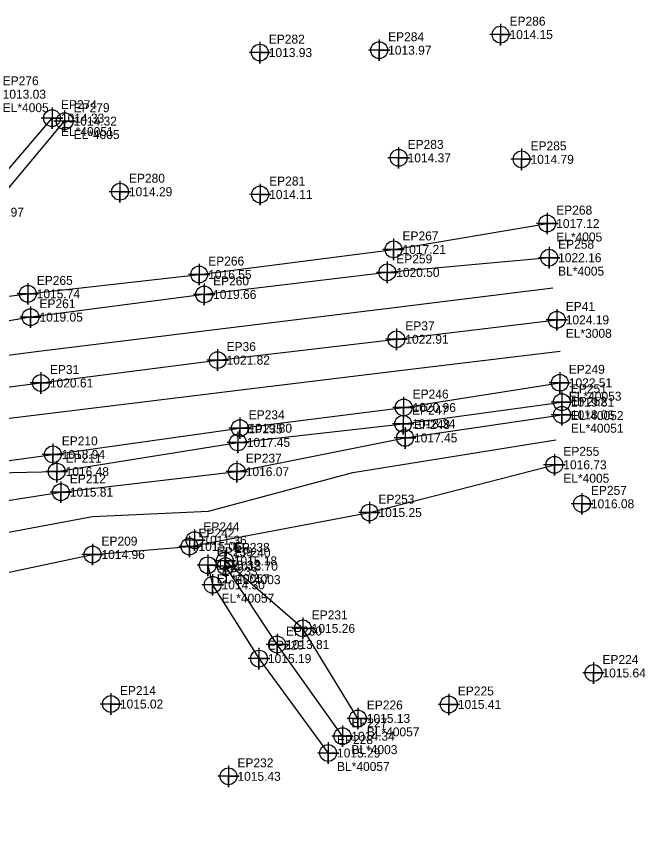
# Model space of a CAD drawing. Extents: x 1382561 to 1383039, y 884068 to 884307.
# Drawn here: x 1382864 to 1383039.5, y 884076 to 884306.8 of the extents above; entities that cross this region are included whole.
import ezdxf

# ---------------------------------------------------------------- set-up
doc = ezdxf.new("R2010")
doc.units = 0
for name, color, linetype in [('Exist DTM Breakline', 7, 'Continuous'), ('Exist DTM Breakline Cogo Comment', 7, 'Continuous'), ('Exist DTM Breakline Cogo Elevation', 7, 'Continuous'), ('Exist DTM Breakline Cogo Number', 7, 'Continuous'), ('Exist DTM Breakline Cogo Point CELL', 7, 'Continuous'), ('Exist DTM Crownline', 7, 'Continuous'), ('Exist DTM Crownline Cogo Comment', 7, 'Continuous'), ('Exist DTM Crownline Cogo Elevation', 7, 'Continuous'), ('Exist DTM Crownline Cogo Number', 7, 'Continuous'), ('Exist DTM Crownline Cogo Point CELL', 7, 'Continuous'), ('Exist DTM Drainline', 7, 'Continuous'), ('Exist DTM Drainline Cogo Comment', 7, 'Continuous'), ('Exist DTM Drainline Cogo Elevation', 7, 'Continuous'), ('Exist DTM Drainline Cogo Number', 7, 'Continuous'), ('Exist DTM Drainline Cogo Point CELL', 7, 'Continuous'), ('Exist DTM Regular Point CELL', 7, 'Continuous'), ('Exist DTM Regular Point Cogo Elevation', 7, 'Continuous'), ('Exist DTM Regular Point Cogo Number', 7, 'Continuous'), ('Exist Hydro Stream or Body of Water', 7, 'Continuous'), ('Exist Roads EOP', 7, 'Continuous')]:
    doc.layers.add(name, color=color, linetype=linetype)

msp = doc.modelspace()

# ---------------------------------------------------------------- linework, layer by layer
at = {"layer": 'Exist DTM Breakline'}
msp.add_line((1382845.6099, 884239.6486), (1382877.4407, 884277.6733), dxfattribs=at)
for points in [[(1382841.0523, 884232.5474), (1382851.5055, 884252.2797), (1382873.9304, 884278.5226)], [(1382831.3079, 884219.8003), (1382838.3409, 884225.9989), (1382867.1646, 884229.517), (1382914.9927, 884234.9104), (1382969.1885, 884241.9138), (1383012.0651, 884249.1214)], [(1383012.5976, 884239.5988), (1382967.445, 884235.5084), (1382916.3525, 884229.3577), (1382867.9342, 884223.0248), (1382833.9892, 884217.1167)], [(1382831.6499, 884178.864), (1382874.1379, 884184.7558), (1382926.2901, 884192.0506), (1382972.0132, 884197.818), (1383015.5779, 884204.7229)], [(1382833.366, 884179.0369), (1382875.2238, 884179.95), (1382925.7486, 884188.0979), (1382971.8534, 884193.2925), (1383016.146, 884199.3057)], [(1382816.5885, 884178.0325), (1382823.1269, 884170.7527), (1382834.2668, 884167.6062), (1382876.3893, 884174.2104), (1382925.471, 884179.9339), (1382972.4064, 884189.3415), (1383016.1626, 884195.7946)], [(1382751.4287, 884075.9856), (1382771.8716, 884111.3375), (1382784.8942, 884142.8663), (1382794.19, 884164.1279), (1382801.7626, 884181.793), (1382802.1903, 884175.7622), (1382803.9822, 884162.9447), (1382834.7331, 884146.1448), (1382885.2227, 884156.817), (1382912.2708, 884159.0791), (1382962.484, 884168.5252), (1383014.0488, 884181.852)], [(1382959.2316, 884111.1176), (1382943.8664, 884136.2293), (1382922.1236, 884155.0649)], [(1382917.3998, 884153.8373), (1382918.7216, 884148.3822), (1382931.6569, 884127.8044), (1382950.9324, 884101.4825)]]:
    msp.add_lwpolyline(points, dxfattribs=at)
at = {"layer": 'Exist DTM Breakline Cogo Point CELL'}
for points in [[(1382873.9304, 884281.5226), (1382873.9304, 884275.5226), (1382873.9304, 884278.5226), (1382876.9304, 884278.5226), (1382870.9304, 884278.5226)], [(1382877.4407, 884280.6733), (1382877.4407, 884274.6733), (1382877.4407, 884277.6733), (1382880.4407, 884277.6733), (1382874.4407, 884277.6733)], [(1383012.0651, 884252.1214), (1383012.0651, 884246.1214), (1383012.0651, 884249.1214), (1383015.0651, 884249.1214), (1383009.0651, 884249.1214)], [(1382969.1885, 884244.9138), (1382969.1885, 884238.9138), (1382969.1885, 884241.9138), (1382972.1885, 884241.9138), (1382966.1885, 884241.9138)], [(1383012.5976, 884242.5988), (1383012.5976, 884236.5988), (1383012.5976, 884239.5988), (1383015.5976, 884239.5988), (1383009.5976, 884239.5988)], [(1382914.9927, 884237.9104), (1382914.9927, 884231.9104), (1382914.9927, 884234.9104), (1382917.9927, 884234.9104), (1382911.9927, 884234.9104)], [(1382967.445, 884238.5084), (1382967.445, 884232.5084), (1382967.445, 884235.5084), (1382970.445, 884235.5084), (1382964.445, 884235.5084)], [(1382867.1646, 884232.517), (1382867.1646, 884226.517), (1382867.1646, 884229.517), (1382870.1646, 884229.517), (1382864.1646, 884229.517)], [(1382916.3525, 884232.3577), (1382916.3525, 884226.3577), (1382916.3525, 884229.3577), (1382919.3525, 884229.3577), (1382913.3525, 884229.3577)], [(1382867.9342, 884226.0248), (1382867.9342, 884220.0248), (1382867.9342, 884223.0248), (1382870.9342, 884223.0248), (1382864.9342, 884223.0248)], [(1383015.5779, 884207.7229), (1383015.5779, 884201.7229), (1383015.5779, 884204.7229), (1383018.5779, 884204.7229), (1383012.5779, 884204.7229)], [(1382972.0132, 884200.818), (1382972.0132, 884194.818), (1382972.0132, 884197.818), (1382975.0132, 884197.818), (1382969.0132, 884197.818)], [(1383016.146, 884202.3057), (1383016.146, 884196.3057), (1383016.146, 884199.3057), (1383019.146, 884199.3057), (1383013.146, 884199.3057)], [(1383016.1626, 884198.7946), (1383016.1626, 884192.7946), (1383016.1626, 884195.7946), (1383019.1626, 884195.7946), (1383013.1626, 884195.7946)], [(1382971.8534, 884196.2925), (1382971.8534, 884190.2925), (1382971.8534, 884193.2925), (1382974.8534, 884193.2925), (1382968.8534, 884193.2925)], [(1382926.2901, 884195.0506), (1382926.2901, 884189.0506), (1382926.2901, 884192.0506), (1382929.2901, 884192.0506), (1382923.2901, 884192.0506)], [(1382972.4064, 884192.3415), (1382972.4064, 884186.3415), (1382972.4064, 884189.3415), (1382975.4064, 884189.3415), (1382969.4064, 884189.3415)], [(1382925.7486, 884191.0979), (1382925.7486, 884185.0979), (1382925.7486, 884188.0979), (1382928.7486, 884188.0979), (1382922.7486, 884188.0979)], [(1382874.1379, 884187.7558), (1382874.1379, 884181.7558), (1382874.1379, 884184.7558), (1382877.1379, 884184.7558), (1382871.1379, 884184.7558)], [(1383014.0488, 884184.852), (1383014.0488, 884178.852), (1383014.0488, 884181.852), (1383017.0488, 884181.852), (1383011.0488, 884181.852)], [(1382875.2238, 884182.95), (1382875.2238, 884176.95), (1382875.2238, 884179.95), (1382878.2238, 884179.95), (1382872.2238, 884179.95)], [(1382925.471, 884182.9339), (1382925.471, 884176.9339), (1382925.471, 884179.9339), (1382928.471, 884179.9339), (1382922.471, 884179.9339)], [(1382876.3893, 884177.2104), (1382876.3893, 884171.2104), (1382876.3893, 884174.2104), (1382879.3893, 884174.2104), (1382873.3893, 884174.2104)], [(1382962.484, 884171.5252), (1382962.484, 884165.5252), (1382962.484, 884168.5252), (1382965.484, 884168.5252), (1382959.484, 884168.5252)], [(1382912.2708, 884162.0791), (1382912.2708, 884156.0791), (1382912.2708, 884159.0791), (1382915.2708, 884159.0791), (1382909.2708, 884159.0791)], [(1382885.2227, 884159.817), (1382885.2227, 884153.817), (1382885.2227, 884156.817), (1382888.2227, 884156.817), (1382882.2227, 884156.817)], [(1382922.1236, 884158.0649), (1382922.1236, 884152.0649), (1382922.1236, 884155.0649), (1382925.1236, 884155.0649), (1382919.1236, 884155.0649)], [(1382917.3998, 884156.8373), (1382917.3998, 884150.8373), (1382917.3998, 884153.8373), (1382920.3998, 884153.8373), (1382914.3998, 884153.8373)], [(1382918.7216, 884151.3822), (1382918.7216, 884145.3822), (1382918.7216, 884148.3822), (1382921.7216, 884148.3822), (1382915.7216, 884148.3822)], [(1382943.8664, 884139.2293), (1382943.8664, 884133.2293), (1382943.8664, 884136.2293), (1382946.8664, 884136.2293), (1382940.8664, 884136.2293)], [(1382931.6569, 884130.8044), (1382931.6569, 884124.8044), (1382931.6569, 884127.8044), (1382934.6569, 884127.8044), (1382928.6569, 884127.8044)], [(1382959.2316, 884114.1176), (1382959.2316, 884108.1176), (1382959.2316, 884111.1176), (1382962.2316, 884111.1176), (1382956.2316, 884111.1176)], [(1382950.9324, 884104.4825), (1382950.9324, 884098.4825), (1382950.9324, 884101.4825), (1382953.9324, 884101.4825), (1382947.9324, 884101.4825)]]:
    msp.add_lwpolyline(points, dxfattribs=at)
for centre in [(1382873.9304, 884278.5226), (1382877.4407, 884277.6733), (1383012.0651, 884249.1214), (1382969.1885, 884241.9138), (1383012.5976, 884239.5988), (1382967.445, 884235.5084), (1382914.9927, 884234.9104), (1382867.1646, 884229.517), (1382916.3525, 884229.3577), (1382867.9342, 884223.0248), (1383015.5779, 884204.7229), (1383016.146, 884199.3057), (1382972.0132, 884197.818), (1383016.1626, 884195.7946), (1382926.2901, 884192.0506), (1382971.8534, 884193.2925), (1382972.4064, 884189.3415), (1382925.7486, 884188.0979), (1382874.1379, 884184.7558), (1382875.2238, 884179.95), (1382925.471, 884179.9339), (1383014.0488, 884181.852), (1382876.3893, 884174.2104), (1382962.484, 884168.5252), (1382885.2227, 884156.817), (1382912.2708, 884159.0791), (1382922.1236, 884155.0649), (1382917.3998, 884153.8373), (1382918.7216, 884148.3822), (1382943.8664, 884136.2293), (1382931.6569, 884127.8044), (1382959.2316, 884111.1176), (1382950.9324, 884101.4825)]:
    msp.add_circle(centre, 2.344, dxfattribs=at)
at = {"layer": 'Exist DTM Crownline'}
msp.add_lwpolyline([(1382818.0568, 884197.9832), (1382870.8354, 884204.6592), (1382920.1217, 884211.0486), (1382969.977, 884216.8417), (1383014.7296, 884222.2543)], dxfattribs=at)
at = {"layer": 'Exist DTM Crownline Cogo Point CELL'}
for points in [[(1383014.7296, 884225.2543), (1383014.7296, 884219.2543), (1383014.7296, 884222.2543), (1383017.7296, 884222.2543), (1383011.7296, 884222.2543)], [(1382969.977, 884219.8417), (1382969.977, 884213.8417), (1382969.977, 884216.8417), (1382972.977, 884216.8417), (1382966.977, 884216.8417)], [(1382920.1217, 884214.0486), (1382920.1217, 884208.0486), (1382920.1217, 884211.0486), (1382923.1217, 884211.0486), (1382917.1217, 884211.0486)], [(1382870.8354, 884207.6592), (1382870.8354, 884201.6592), (1382870.8354, 884204.6592), (1382873.8354, 884204.6592), (1382867.8354, 884204.6592)]]:
    msp.add_lwpolyline(points, dxfattribs=at)
for centre in [(1383014.7296, 884222.2543), (1382969.977, 884216.8417), (1382920.1217, 884211.0486), (1382870.8354, 884204.6592)]:
    msp.add_circle(centre, 2.344, dxfattribs=at)
at = {"layer": 'Exist DTM Drainline'}
msp.add_lwpolyline([(1382954.9397, 884106.1701), (1382936.6947, 884131.7417), (1382922.3411, 884153.5703)], dxfattribs=at)
at = {"layer": 'Exist DTM Drainline Cogo Point CELL'}
for points in [[(1382922.3411, 884156.5703), (1382922.3411, 884150.5703), (1382922.3411, 884153.5703), (1382925.3411, 884153.5703), (1382919.3411, 884153.5703)], [(1382936.6947, 884134.7417), (1382936.6947, 884128.7417), (1382936.6947, 884131.7417), (1382939.6947, 884131.7417), (1382933.6947, 884131.7417)], [(1382954.9397, 884109.1701), (1382954.9397, 884103.1701), (1382954.9397, 884106.1701), (1382957.9397, 884106.1701), (1382951.9397, 884106.1701)]]:
    msp.add_lwpolyline(points, dxfattribs=at)
for centre in [(1382922.3411, 884153.5703), (1382936.6947, 884131.7417), (1382954.9397, 884106.1701)]:
    msp.add_circle(centre, 2.344, dxfattribs=at)
at = {"layer": 'Exist DTM Regular Point CELL'}
for points in [[(1382999.0427, 884304.8011), (1382999.0427, 884298.8011), (1382999.0427, 884301.8011), (1383002.0427, 884301.8011), (1382996.0427, 884301.8011)], [(1382965.1824, 884300.4508), (1382965.1824, 884294.4508), (1382965.1824, 884297.4508), (1382968.1824, 884297.4508), (1382962.1824, 884297.4508)], [(1382931.8918, 884299.7936), (1382931.8918, 884293.7936), (1382931.8918, 884296.7936), (1382934.8918, 884296.7936), (1382928.8918, 884296.7936)], [(1382970.6166, 884270.4352), (1382970.6166, 884264.4352), (1382970.6166, 884267.4352), (1382973.6166, 884267.4352), (1382967.6166, 884267.4352)], [(1383004.9029, 884270.028), (1383004.9029, 884264.028), (1383004.9029, 884267.028), (1383007.9029, 884267.028), (1383001.9029, 884267.028)], [(1382892.8819, 884260.9949), (1382892.8819, 884254.9949), (1382892.8819, 884257.9949), (1382895.8819, 884257.9949), (1382889.8819, 884257.9949)], [(1382932.0019, 884260.2242), (1382932.0019, 884254.2242), (1382932.0019, 884257.2242), (1382935.0019, 884257.2242), (1382929.0019, 884257.2242)], [(1383021.7444, 884173.9691), (1383021.7444, 884167.9691), (1383021.7444, 884170.9691), (1383024.7444, 884170.9691), (1383018.7444, 884170.9691)], [(1382913.6496, 884163.8177), (1382913.6496, 884157.8177), (1382913.6496, 884160.8177), (1382916.6496, 884160.8177), (1382910.6496, 884160.8177)], [(1383024.9683, 884126.7958), (1383024.9683, 884120.7958), (1383024.9683, 884123.7958), (1383027.9683, 884123.7958), (1383021.9683, 884123.7958)], [(1382890.3689, 884118.1404), (1382890.3689, 884112.1404), (1382890.3689, 884115.1404), (1382893.3689, 884115.1404), (1382887.3689, 884115.1404)], [(1382984.6236, 884118.0233), (1382984.6236, 884112.0233), (1382984.6236, 884115.0233), (1382987.6236, 884115.0233), (1382981.6236, 884115.0233)], [(1382923.1436, 884097.9796), (1382923.1436, 884091.9796), (1382923.1436, 884094.9796), (1382926.1436, 884094.9796), (1382920.1436, 884094.9796)]]:
    msp.add_lwpolyline(points, dxfattribs=at)
for centre in [(1382999.0427, 884301.8011), (1382931.8918, 884296.7936), (1382965.1824, 884297.4508), (1382970.6166, 884267.4352), (1383004.9029, 884267.028), (1382892.8819, 884257.9949), (1382932.0019, 884257.2242), (1383021.7444, 884170.9691), (1382913.6496, 884160.8177), (1383024.9683, 884123.7958), (1382890.3689, 884115.1404), (1382984.6236, 884115.0233), (1382923.1436, 884094.9796)]:
    msp.add_circle(centre, 2.344, dxfattribs=at)
at = {"layer": 'Exist Hydro Stream or Body of Water'}
msp.add_lwpolyline([(1382804.2469, 884181.3186), (1382804.7285, 884175.5016), (1382808.6563, 884165.6118), (1382834.3787, 884157.9417), (1382885.1736, 884167.4669), (1382917.5577, 884168.9128), (1382957.8255, 884179.6802), (1383014.491, 884188.8061)], dxfattribs=at)
at = {"layer": 'Exist Roads EOP'}
for points in [[(1382822.1133, 884207.287), (1382869.4756, 884213.4311), (1382919.3634, 884219.5355), (1382969.3733, 884225.6957), (1383013.6331, 884231.1593)], [(1382813.3303, 884188.8665), (1382871.1957, 884195.987), (1382921.2905, 884202.1311), (1382970.8421, 884208.1022), (1383015.6768, 884213.5139)]]:
    msp.add_lwpolyline(points, dxfattribs=at)

# ---------------------------------------------------------------- texts
at = {"layer": 'Exist DTM Breakline Cogo Comment'}
for s, p in [('EL*4005', (1382860.165, 884280.1804)), ('EL*40051', (1382876.4304, 884273.5226)), ('EL*4005', (1382879.9407, 884272.6733)), ('EL*4005', (1383014.5651, 884244.1214)), ('BL*4005', (1383015.0976, 884234.5988)), ('EL*40053', (1383018.0779, 884199.7229)), ('EL*40052', (1383018.646, 884194.3057)), ('EL*40051', (1383018.6626, 884190.7946)), ('EL*4005', (1383016.5488, 884176.852)), ('EL*40057', (1382919.8998, 884148.8373)), ('EL*40057', (1382921.2216, 884143.3822)), ('BL*40057', (1382961.7316, 884106.1176)), ('BL*40057', (1382953.4324, 884096.4825))]:
    msp.add_text(s, height=2.5, dxfattribs=at).set_placement(p)
at = {"layer": 'Exist DTM Breakline Cogo Elevation'}
for s, p in [('1013.03', (1382860.165, 884283.9304)), ('1014.33', (1382876.4304, 884277.2726)), ('1014.32', (1382879.9407, 884276.4233)), ('1015.97', (1382854.0055, 884251.0297)), ('1017.12', (1383014.5651, 884247.8714)), ('1017.21', (1382971.6885, 884240.6638)), ('1022.16', (1383015.0976, 884238.3488)), ('1016.55', (1382917.4927, 884233.6604)), ('1020.50', (1382969.945, 884234.2584)), ('1015.74', (1382869.6646, 884228.267)), ('1019.66', (1382918.8525, 884228.1077)), ('1019.05', (1382870.4342, 884221.7748)), ('1022.51', (1383018.0779, 884203.4729)), ('1020.96', (1382974.5132, 884196.568)), ('1019.81', (1383018.646, 884198.0557)), ('1018.06', (1383018.6626, 884194.5446)), ('1018.34', (1382974.3534, 884192.0425)), ('1019.80', (1382928.7901, 884190.8006)), ('1017.45', (1382928.2486, 884186.8479)), ('1017.45', (1382974.9064, 884188.0915)), ('1018.94', (1382876.6379, 884183.5058)), ('1016.73', (1383016.5488, 884180.602)), ('1016.48', (1382877.7238, 884178.7)), ('1016.07', (1382927.971, 884178.6839)), ('1015.81', (1382878.8893, 884172.9604)), ('1015.25', (1382964.984, 884167.2752)), ('1015.05', (1382914.7708, 884157.8291)), ('1014.96', (1382887.7227, 884155.567)), ('1015.32', (1382919.8998, 884152.5873)), ('1015.18', (1382924.6236, 884153.8149)), ('1014.30', (1382921.2216, 884147.1322)), ('1015.26', (1382946.3664, 884134.9793)), ('1015.19', (1382934.1569, 884126.5544)), ('1015.13', (1382961.7316, 884109.8676)), ('1015.29', (1382953.4324, 884100.2325))]:
    msp.add_text(s, height=2.5, dxfattribs=at).set_placement(p)
at = {"layer": 'Exist DTM Breakline Cogo Number'}
for s, p in [('EP276', (1382860.165, 884287.6804)), ('EP274', (1382876.4304, 884281.0226)), ('EP279', (1382879.9407, 884280.1733)), ('EP268', (1383014.5651, 884251.6214)), ('EP267', (1382971.6885, 884244.4138)), ('EP258', (1383015.0976, 884242.0988)), ('EP266', (1382917.4927, 884237.4104)), ('EP259', (1382969.945, 884238.0084)), ('EP265', (1382869.6646, 884232.017)), ('EP260', (1382918.8525, 884231.8577)), ('EP261', (1382870.4342, 884225.5248)), ('EP249', (1383018.0779, 884207.2229)), ('EP251', (1383018.646, 884201.8057)), ('EP246', (1382974.5132, 884200.318)), ('EP252', (1383018.6626, 884198.2946)), ('EP234', (1382928.7901, 884194.5506)), ('EP247', (1382974.3534, 884195.7925)), ('EP248', (1382974.9064, 884191.8415)), ('EP235', (1382928.2486, 884190.5979)), ('EP210', (1382876.6379, 884187.2558)), ('EP255', (1383016.5488, 884184.352)), ('EP211', (1382877.7238, 884182.45)), ('EP237', (1382927.971, 884182.4339)), ('EP212', (1382878.8893, 884176.7104)), ('EP253', (1382964.984, 884171.0252)), ('EP242', (1382914.7708, 884161.5791)), ('EP209', (1382887.7227, 884159.317)), ('EP238', (1382924.6236, 884157.5649)), ('EP239', (1382919.8998, 884156.3373)), ('EP233', (1382921.2216, 884150.8822)), ('EP231', (1382946.3664, 884138.7293)), ('EP229', (1382934.1569, 884130.3044)), ('EP226', (1382961.7316, 884113.6176)), ('EP228', (1382953.4324, 884103.9825))]:
    msp.add_text(s, height=2.5, dxfattribs=at).set_placement(p)
at = {"layer": 'Exist DTM Crownline Cogo Comment'}
msp.add_text('EL*3008', height=2.5, dxfattribs=at).set_placement((1383017.2296, 884217.2543))
at = {"layer": 'Exist DTM Crownline Cogo Elevation'}
for s, p in [('1024.19', (1383017.2296, 884221.0043)), ('1022.91', (1382972.477, 884215.5917)), ('1021.82', (1382922.6217, 884209.7986)), ('1020.61', (1382873.3354, 884203.4092))]:
    msp.add_text(s, height=2.5, dxfattribs=at).set_placement(p)
at = {"layer": 'Exist DTM Crownline Cogo Number'}
for s, p in [('EP41', (1383017.2296, 884224.7543)), ('EP37', (1382972.477, 884219.3417)), ('EP36', (1382922.6217, 884213.5486)), ('EP31', (1382873.3354, 884207.1592))]:
    msp.add_text(s, height=2.5, dxfattribs=at).set_placement(p)
at = {"layer": 'Exist DTM Drainline Cogo Comment'}
for s, p in [('EL*4003', (1382924.8411, 884148.5703)), ('BL*4003', (1382957.4397, 884101.1701))]:
    msp.add_text(s, height=2.5, dxfattribs=at).set_placement(p)
at = {"layer": 'Exist DTM Drainline Cogo Elevation'}
for s, p in [('1013.70', (1382924.8411, 884152.3203)), ('1013.81', (1382939.1947, 884130.4917)), ('1014.34', (1382957.4397, 884104.9201))]:
    msp.add_text(s, height=2.5, dxfattribs=at).set_placement(p)
at = {"layer": 'Exist DTM Drainline Cogo Number'}
for s, p in [('EP240', (1382924.8411, 884156.0703)), ('EP230', (1382939.1947, 884134.2417)), ('EP227', (1382957.4397, 884108.6701))]:
    msp.add_text(s, height=2.5, dxfattribs=at).set_placement(p)
at = {"layer": 'Exist DTM Regular Point Cogo Elevation'}
for s, p in [('1014.15', (1383001.5427, 884300.5511)), ('1013.93', (1382934.3918, 884295.5436)), ('1013.97', (1382967.6824, 884296.2008)), ('1014.37', (1382973.1166, 884266.1852)), ('1014.79', (1383007.4029, 884265.778)), ('1014.29', (1382895.3819, 884256.7449)), ('1014.11', (1382934.5019, 884255.9742)), ('1016.08', (1383024.2444, 884169.7191)), ('1011.36', (1382916.1496, 884159.5677)), ('1015.64', (1383027.4683, 884122.5458)), ('1015.02', (1382892.8689, 884113.8904)), ('1015.41', (1382987.1236, 884113.7733)), ('1015.43', (1382925.6436, 884093.7296))]:
    msp.add_text(s, height=2.5, dxfattribs=at).set_placement(p)
at = {"layer": 'Exist DTM Regular Point Cogo Number'}
for s, p in [('EP286', (1383001.5427, 884304.3011)), ('EP284', (1382967.6824, 884299.9508)), ('EP282', (1382934.3918, 884299.2936)), ('EP283', (1382973.1166, 884269.9352)), ('EP285', (1383007.4029, 884269.528)), ('EP280', (1382895.3819, 884260.4949)), ('EP281', (1382934.5019, 884259.7242)), ('EP257', (1383024.2444, 884173.4691)), ('EP244', (1382916.1496, 884163.3177)), ('EP224', (1383027.4683, 884126.2958)), ('EP214', (1382892.8689, 884117.6404)), ('EP225', (1382987.1236, 884117.5233)), ('EP232', (1382925.6436, 884097.4796))]:
    msp.add_text(s, height=2.5, dxfattribs=at).set_placement(p)

doc.saveas('drawing.dxf')
